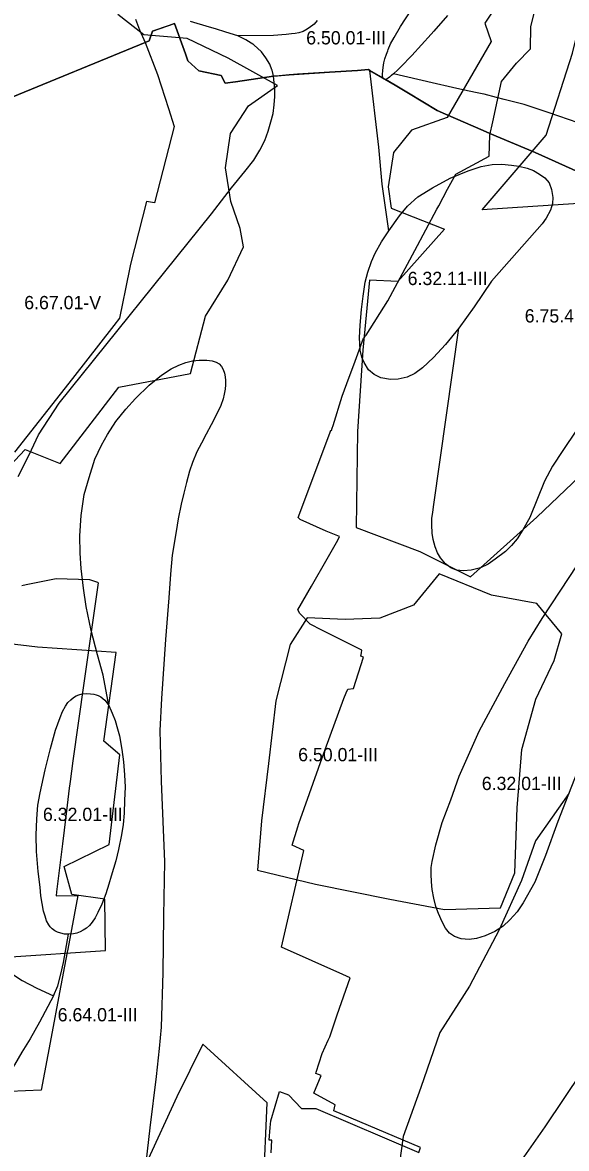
# Model space of a CAD drawing. Extents: x -555156 to -540209, y -1046851 to -1035695.
# Drawn here: x -543686 to -543276, y -1041405 to -1040556 of the extents above; entities that cross this region are included whole.
import ezdxf

# ---------------------------------------------------------------- set-up
doc = ezdxf.new("R2010")
doc.units = 0
for name, color, linetype in [('Vrstva 12', 7, 'Continuous'), ('Vrstva 27', 7, 'Continuous'), ('Vrstva 28', 7, 'Continuous'), ('Vrstva 29', 7, 'Continuous')]:
    doc.layers.add(name, color=color, linetype=linetype)

msp = doc.modelspace()

# ---------------------------------------------------------------- linework, layer by layer
at = {"layer": 'Vrstva 12'}
for points in [[(-543498.53, -1041408.44), (-543497.81, -1041398.96), (-543499.81, -1041398.89), (-543499.08, -1041389.42), (-543498.7, -1041384.38), (-543492.02, -1041362.08), (-543485.34, -1041364.83), (-543475.49, -1041375.02), (-543464.74, -1041375.01), (-543386.99, -1041408.3), (-543385.74, -1041404.41), (-543451.18, -1041376.73), (-543450.07, -1041372.36), (-543466.16, -1041363.35), (-543460.73, -1041350.09), (-543464.77, -1041348.56), (-543464.41, -1041347.63), (-543459.93, -1041333.56), (-543455.39, -1041323.59), (-543454.25, -1041321.08), (-543448.53, -1041304.5), (-543438.87, -1041276.51), (-543444.45, -1041273.91), (-543490.62, -1041253.26), (-543473.78, -1041180.39), (-543482.45, -1041176.48), (-543478.32, -1041162.62), (-543477.44, -1041160.15), (-543458.7, -1041107.1), (-543457.94, -1041105.02), (-543457.66, -1041104.26), (-543443.69, -1041065.97), (-543441.85, -1041061.61), (-543440.65, -1041058.78), (-543436.23, -1041058.23), (-543428.67, -1041034.6), (-543430.7, -1041033.81), (-543430.31, -1041031.4), (-543429.99, -1041029.48), (-543454.04, -1041017.4), (-543460.13, -1041014.34), (-543468.96, -1041009.9), (-543476.75, -1041001.8), (-543478.2, -1040998.98), (-543468, -1040981.18), (-543456.25, -1040960.65), (-543448.12, -1040946.45), (-543446.912347, -1040943.566929), (-543456.92, -1040939.75), (-543476.44, -1040930.98), (-543478.04, -1040929.37), (-543454.19, -1040865.7), (-543453.37, -1040863.52), (-543452.79, -1040863.73), (-543452.28, -1040862.01), (-543451.66, -1040859.91), (-543444.94, -1040837.84), (-543441.39, -1040828.27), (-543435.13, -1040811.43), (-543428.68, -1040794.07), (-543426.78, -1040791.75), (-543410.45, -1040765.88), (-543390.01, -1040727.91), (-543373.27, -1040696.81), (-543371.93, -1040694.31), (-543365.25, -1040681.9), (-543359.07, -1040670.43), (-543333.92, -1040656.78), (-543333.49, -1040641.01), (-543331.24, -1040631.05), (-543324.56, -1040600.61), (-543313.33, -1040586.75), (-543302.82, -1040575.86), (-543302.36, -1040559.22), (-543297.93, -1040541.28)], [(-543600.86, -1040553.7), (-543597.77, -1040561.73), (-543593.47, -1040571.22), (-543584.26, -1040595.42), (-543575.95, -1040621.03), (-543571.55, -1040634.6), (-543586.56, -1040692.2), (-543592.51, -1040691.16)], [(-543592.51, -1040691.16), (-543604.48, -1040738.44), (-543608.53, -1040758.07), (-543610.32, -1040766.76), (-543612.86, -1040779.08), (-543617.16, -1040784.58), (-543648.44, -1040824.55), (-543691.97, -1040880.16)], [(-543686.62, -1040980.68), (-543683.27, -1040979.99), (-543660.69, -1040975.32), (-543635.43, -1040976.2), (-543629.34, -1040978.2), (-543629.01, -1040978.73), (-543639.72, -1041054.36), (-543648.01, -1041112.9), (-543650.18, -1041128.46), (-543650.42, -1041130.19), (-543650.87, -1041133.37), (-543653.47, -1041154.92), (-543655.95, -1041175.43), (-543660.32, -1041211.61), (-543660.69, -1041214.71), (-543644.41, -1041214.39), (-543651.97, -1041254.77), (-543652.44, -1041257.25), (-543658.14, -1041287.58), (-543664.44, -1041321.12), (-543671.97, -1041361.22), (-543719.58, -1041363.23)]]:
    msp.add_lwpolyline(points, dxfattribs=at)
at = {"layer": 'Vrstva 28'}
for points in [[(-543413.96, -1040590.05), (-543413.45, -1040586.63), (-543412.6, -1040583.56), (-543411.32, -1040579.97), (-543410.42, -1040577.52), (-543410.04, -1040576.47), (-543408.24, -1040572.2), (-543405.68, -1040567.33), (-543400.9, -1040559.18), (-543392.87, -1040546.69)], [(-543365.44, -1040550.9), (-543375.76, -1040562.6), (-543377.75, -1040564.86), (-543392.24, -1040581), (-543393.44, -1040582.34), (-543399.32, -1040588.34), (-543402.79, -1040591.8), (-543406.05, -1040594.73)], [(-543702.42, -1040808.65), (-543708.38, -1040743.94), (-543710.96, -1040724.1), (-543714.65, -1040695.64), (-543715.21, -1040672.48), (-543732.41, -1040662.28), (-543766.58, -1040642.03), (-543740.61, -1040631.41), (-543698.83, -1040614.32), (-543593.47, -1040571.22), (-543590.56, -1040569.96), (-543587.92, -1040562.74), (-543571.38, -1040556.86), (-543563.03, -1040579.77)], [(-543496.57, -1040596.65), (-543525.27, -1040600.79), (-543533.08, -1040601.92), (-543536.12, -1040596.1), (-543552.9, -1040592.63), (-543561.17, -1040584.9), (-543563.03, -1040579.77), (-543571.38, -1040556.86), (-543575.41, -1040558.29), (-543587.92, -1040562.74), (-543590.56, -1040569.96), (-543593.47, -1040571.22), (-543698.83, -1040614.32)], [(-543523.53, -1040566.26), (-543532.64, -1040563.27), (-543540.46, -1040560.92), (-543545.04, -1040559.54), (-543559.37, -1040555.25)], [(-543463.73, -1040554.68), (-543466.04, -1040557.24), (-543467.03, -1040558.07), (-543468.6, -1040559.38), (-543471.25, -1040561.17), (-543474.32, -1040562.79), (-543477.56, -1040563.9), (-543480.38, -1040564.41), (-543482.94, -1040564.76), (-543487.21, -1040565.18), (-543496.6, -1040565.78), (-543523.53, -1040566.26)], [(-543496.57, -1040596.65), (-543496.9, -1040595.35), (-543497.71, -1040592.16), (-543497.84, -1040591.67), (-543499.33, -1040587.63), (-543502.32, -1040582.7), (-543505.61, -1040578.22), (-543511.58, -1040572.84), (-543511.85, -1040572.67), (-543512.26, -1040572.42), (-543513.49, -1040571.66), (-543517.41, -1040569.25), (-543523.53, -1040566.26)], [(-543563.03, -1040579.77), (-543561.17, -1040584.9), (-543552.9, -1040592.63), (-543536.12, -1040596.1), (-543533.08, -1040601.92), (-543525.27, -1040600.79), (-543496.57, -1040596.65)], [(-543689.29, -1040898.52), (-543681.03, -1040882.19), (-543673.88, -1040867.03), (-543658.41, -1040843.09), (-543543.36, -1040700.5), (-543528.22, -1040680.75), (-543518.29, -1040668.51), (-543511.51, -1040659.9), (-543507.03, -1040652.27), (-543503.28, -1040645), (-543500.61, -1040638.09), (-543498.55, -1040630.94), (-543496.98, -1040624.64), (-543496.13, -1040618.22), (-543495.53, -1040611.92), (-543495.65, -1040606.47), (-543496.57, -1040596.65)], [(-543496.57, -1040596.65), (-543484.82, -1040595.49), (-543454.33, -1040593.48), (-543433.19, -1040592.18), (-543425.03, -1040591.54), (-543423.93, -1040592.18)], [(-543413.87, -1040598.02), (-543423.93, -1040592.18), (-543425.03, -1040591.54), (-543433.19, -1040592.18), (-543454.33, -1040593.48), (-543478.66, -1040595.08), (-543484.82, -1040595.49), (-543492.41, -1040596.24), (-543496.57, -1040596.65)], [(-543409.7, -1040713.2), (-543414.52, -1040677.95), (-543417.12, -1040650.12), (-543423.93, -1040592.18)], [(-543423.93, -1040592.18), (-543404.86, -1040603.25)], [(-543413.87, -1040598.02), (-543414.06, -1040597.53), (-543414.28, -1040596.22), (-543414.34, -1040594.55), (-543414.23, -1040592.99), (-543414.16, -1040592.21), (-543413.96, -1040590.05)], [(-543406.05, -1040594.73), (-543407.57, -1040595.99), (-543407.76, -1040596.15), (-543409.1, -1040597.21), (-543410.16, -1040598), (-543410.97, -1040598.56), (-543411.41, -1040598.84), (-543411.75, -1040598.97)], [(-543091.12, -1040712.41), (-543111.91, -1040700.84), (-543134.91, -1040687.76), (-543164.45, -1040672.33), (-543174.27, -1040667.88), (-543176.28, -1040666.97), (-543193.18, -1040659.82), (-543201.63, -1040656.25), (-543228.82, -1040646.05), (-543266.64, -1040631.83), (-543288.6, -1040624.24), (-543307.42, -1040617.96), (-543322.58, -1040614.04), (-543328.36, -1040612.54), (-543337.74, -1040610.12), (-543337.84, -1040610.1), (-543342.85, -1040609.11), (-543353.68, -1040606.98), (-543361.64, -1040605.12), (-543376.95, -1040601.54), (-543406.05, -1040594.73)], [(-543412.12, -1040599.04), (-543413.87, -1040598.02)], [(-543411.75, -1040598.97), (-543412.12, -1040599.04)], [(-543085.78, -1040738.2), (-543101.67, -1040732.49), (-543140.14, -1040717.52), (-543174.28, -1040705.94), (-543210.23, -1040692.22), (-543217.71, -1040689.38), (-543238.43, -1040681.52), (-543299.21, -1040654.19), (-543333.45, -1040639.76), (-543338.53, -1040637.62), (-543366.74, -1040625.24), (-543373.17, -1040622.42), (-543394.76, -1040609.36), (-543404.86, -1040603.25), (-543412.12, -1040599.04)], [(-543404.86, -1040603.25), (-543394.76, -1040609.36), (-543373.17, -1040622.42), (-543366.74, -1040625.24), (-543338.53, -1040637.62), (-543333.45, -1040639.76), (-543299.21, -1040654.19), (-543238.43, -1040681.52), (-543217.71, -1040689.38), (-543210.23, -1040692.22), (-543174.28, -1040705.94), (-543140.14, -1040717.52), (-543101.67, -1040732.49), (-543085.78, -1040738.2)], [(-543409.7, -1040713.2), (-543401.56, -1040701.79), (-543395.62, -1040694.52), (-543387.63, -1040687.61), (-543376.61, -1040680.82), (-543363.29, -1040673.43), (-543349.84, -1040667.86), (-543340.03, -1040664.59), (-543331.68, -1040663.13), (-543324.29, -1040662.89), (-543317.14, -1040663.62)], [(-543317.14, -1040663.62), (-543311.45, -1040664.35), (-543305.16, -1040666.04), (-543300.43, -1040667.62), (-543295.83, -1040670.4), (-543291.83, -1040673.31), (-543288.56, -1040677.07), (-543286.75, -1040682.04), (-543285.9, -1040687.97), (-543286.02, -1040692.58), (-543287.72, -1040697.55), (-543290.99, -1040703.73), (-543293.97, -1040708.02), (-543332.07, -1040751.25), (-543345.15, -1040770.52), (-543356.78, -1040786.63)], [(-543356.78, -1040786.63), (-543366.95, -1040798.99), (-543375.91, -1040808.69), (-543384.15, -1040816.44), (-543390.08, -1040820.68), (-543395.78, -1040823.59), (-543402.56, -1040825.17), (-543408.37, -1040825.41), (-543415.64, -1040824.08), (-543420.72, -1040821.65), (-543425.08, -1040817.9), (-543428.35, -1040812.44), (-543430.05, -1040808.57), (-543431.14, -1040803.11), (-543431.62, -1040798.27), (-543431.68, -1040793.9), (-543431.19, -1040784.21), (-543430.34, -1040772.58), (-543428.89, -1040762.4), (-543427.44, -1040751.86), (-543425.5, -1040744.35), (-543422.71, -1040736.35), (-543419.93, -1040730.05), (-543415.08, -1040721.44), (-543409.7, -1040713.2)], [(-543268, -1040863.45), (-543278.38, -1040878.72), (-543286.23, -1040890.59), (-543292.22, -1040901.95), (-543303.12, -1040929.34), (-543308.45, -1040938.67), (-543312.69, -1040945.33), (-543316.93, -1040950.54), (-543321.53, -1040955.03), (-543329.28, -1040960.72), (-543334.73, -1040964.48), (-543340.54, -1040967.39), (-543347.57, -1040968.96), (-543353.38, -1040969.69), (-543358.47, -1040969.08), (-543362.83, -1040967.39), (-543366.94, -1040964.24), (-543370.58, -1040959.87), (-543372.88, -1040956.12), (-543374.69, -1040951.39), (-543376.15, -1040946.06), (-543376.87, -1040941.09), (-543377.12, -1040934.79), (-543377.12, -1040930.19), (-543376.51, -1040925.22), (-543375.75, -1040919.57), (-543356.78, -1040786.63)], [(-543621.02, -1041071.14), (-543625.26, -1041048.24), (-543629.5, -1041032.97), (-543634.16, -1041014.52), (-543637.98, -1040996.49), (-543640.1, -1040982.71), (-543641.81, -1040967.83), (-543642.65, -1040956.38), (-543642.87, -1040943.23), (-543641.81, -1040927.75), (-543639.47, -1040912.06), (-543635.87, -1040899.12), (-543631.42, -1040885.34), (-543626.55, -1040874.74), (-543621.88, -1040866.68), (-543615.53, -1040856.92), (-543608.11, -1040847.59), (-543600.85, -1040839.67), (-543590.43, -1040829.62), (-543581.23, -1040821.98), (-543573.84, -1040817.26), (-543568.03, -1040814.59), (-543562.82, -1040812.53), (-543557.86, -1040811.32), (-543552.65, -1040810.71), (-543547.08, -1040810.83)], [(-543547.08, -1040810.83), (-543542.91, -1040811.27), (-543539.86, -1040812.17), (-543537.58, -1040813.55), (-543535.78, -1040815.42), (-543534.53, -1040817.71), (-543533.57, -1040820.48), (-543533.01, -1040823.31), (-543532.8, -1040825.95), (-543532.94, -1040829.34), (-543533.22, -1040832.59), (-543533.84, -1040836.26), (-543534.67, -1040839.93), (-543536.33, -1040844.85), (-543539.66, -1040851.77), (-543543.74, -1040859.6), (-543547.49, -1040866.57), (-543551.09, -1040873.22), (-543554.41, -1040879.87), (-543557.67, -1040887.83), (-543560.11, -1040894.52), (-543562.41, -1040903), (-543564.35, -1040911), (-543566.29, -1040919.24), (-543568.59, -1040930.27), (-543570.16, -1040939.84), (-543573.12, -1040957.74), (-543574.39, -1040972.16), (-543575.66, -1040989.97), (-543578.21, -1041021.36), (-543581.17, -1041065.89), (-543582.45, -1041090.06), (-543581.53, -1041128.11), (-543578.94, -1041188.97), (-543579.68, -1041229.79), (-543580.05, -1041272.47), (-543581.53, -1041313.66), (-543583.02, -1041329.8), (-543585.24, -1041350.95), (-543590.06, -1041389.55), (-543594.14, -1041427.03)], [(-543267.79, -1041121.9), (-543281.99, -1041158.59), (-543291.42, -1041184.35), (-543299.54, -1041204.34), (-543308.14, -1041219.86), (-543312.86, -1041226.64), (-543318.31, -1041232.82), (-543323.27, -1041237.43), (-543329.57, -1041241.54), (-543336.84, -1041244.82), (-543343.38, -1041246.76), (-543348.95, -1041247.6), (-543355, -1041247), (-543360.09, -1041245.3), (-543363.85, -1041242.76), (-543366.75, -1041239.12), (-543369.42, -1041234.15), (-543372.08, -1041227.85), (-543374.02, -1041222.76), (-543375.71, -1041216.34), (-543376.92, -1041209.8), (-543377.29, -1041204.1), (-543377.65, -1041198.29), (-543377.65, -1041193.32), (-543376.83, -1041188.83), (-543374.08, -1041176.1), (-543369.42, -1041159.35), (-543362.85, -1041142.18), (-543356.49, -1041124.36), (-543341.44, -1041090.54), (-543322.15, -1041054.55), (-543304.35, -1041022.63), (-543293.87, -1041005.52), (-543253.63, -1040944.47)], [(-543651.37, -1041243.65), (-543652.74, -1041243.66), (-543654.24, -1041243.59), (-543657.17, -1041242.91), (-543659.58, -1041242.12), (-543661.72, -1041241.13), (-543663.58, -1041239.63), (-543665.08, -1041238.05), (-543666.23, -1041236.58), (-543667.83, -1041233.47), (-543669.07, -1041230.07), (-543670.11, -1041226.2), (-543671.29, -1041220.38), (-543672.12, -1041214.63), (-543672.83, -1041208.18), (-543674.28, -1041196.19), (-543675.49, -1041181.16), (-543675.74, -1041168.8), (-543675.25, -1041156.56), (-543674.4, -1041146.27), (-543672.68, -1041136.88), (-543668.92, -1041119.68), (-543664.93, -1041103.56), (-543661.14, -1041089.62), (-543657.7, -1041080.21), (-543655.92, -1041075.62), (-543653.71, -1041071.54), (-543651.73, -1041068.81), (-543649.6, -1041066.75), (-543647.58, -1041065.13), (-543645.56, -1041063.94), (-543643.55, -1041063.03), (-543641.09, -1041062.44), (-543638.13, -1041062.2), (-543634.65, -1041062.28)], [(-543634.65, -1041062.28), (-543632.28, -1041062.6), (-543630.46, -1041062.99), (-543628.84, -1041063.67), (-543627.02, -1041064.7), (-543625.51, -1041065.8), (-543623.85, -1041067.15), (-543622.9, -1041068.37), (-543621.02, -1041071.14)], [(-543621.02, -1041071.14), (-543618.31, -1041076.98), (-543616.25, -1041082.43), (-543614.43, -1041088.61), (-543612.98, -1041094.06), (-543611.16, -1041104.24), (-543609.95, -1041113.57), (-543609.1, -1041123.51), (-543608.65, -1041132.6), (-543609.01, -1041142.42), (-543609.38, -1041152.35), (-543610.1, -1041160.84), (-543611.31, -1041168.59), (-543613.61, -1041179.62), (-543615.67, -1041188.22), (-543619.14, -1041199.93), (-543620.94, -1041205.82), (-543623.16, -1041213.02), (-543626.27, -1041220.98), (-543629.18, -1041227.21), (-543631.32, -1041231.23), (-543633.4, -1041234.48), (-543635.61, -1041237.11), (-543637.83, -1041239.12), (-543640.18, -1041240.58), (-543642.53, -1041241.75), (-543644.95, -1041242.72), (-543647.52, -1041243.28), (-543651.37, -1041243.65)], [(-543367.43, -1041496.06), (-543358.52, -1041484.25), (-543291.66, -1041388.79), (-543235.84, -1041305.67), (-543212.48, -1041277.09), (-543186.52, -1041230.33), (-543130.8, -1041093.03)], [(-543805.56, -1041178.33), (-543801.54, -1041178.79), (-543794.15, -1041180.49), (-543788.46, -1041182.31), (-543781.92, -1041185.21), (-543774.9, -1041189.09), (-543768.48, -1041193.94), (-543763.27, -1041198.54), (-543758.31, -1041204), (-543750.56, -1041213.33), (-543742.85, -1041221.98), (-543723.35, -1041244.88), (-543707.45, -1041261.21), (-543695.16, -1041272.66), (-543686.26, -1041278.59), (-543675.24, -1041284.32), (-543662.75, -1041290.03)], [(-543662.75, -1041290.03), (-543659.48, -1041282.39), (-543657.06, -1041273.67), (-543655.12, -1041264.82), (-543651.37, -1041243.65)], [(-543662.75, -1041290.03), (-543673.29, -1041310.02), (-543680.19, -1041322.38), (-543686.61, -1041332.56), (-543691.99, -1041342.1), (-543697.44, -1041352.64), (-543703.01, -1041364.76), (-543708.22, -1041379.06), (-543712.09, -1041390.81), (-543714.76, -1041402.93)]]:
    msp.add_lwpolyline(points, dxfattribs=at)
at = {"layer": 'Vrstva 29'}
for points in [[(-543203.043003, -1040533.644997), (-543205.959003, -1040596.590006), (-543203.105995, -1040684.815999), (-543266.397004, -1040692.522995), (-543339.110996, -1040697.288998), (-543290.863999, -1040640.979001), (-543270.945994, -1040579.150993), (-543247.329994, -1040483.771991)], [(-543303.915998, -1040506.907994), (-543337.225003, -1040556.489998), (-543332.424005, -1040570.462007), (-543365.693999, -1040627.695991), (-543392.403006, -1040637.375992), (-543406.000005, -1040654.175001), (-543409.990991, -1040680.050991), (-543407.936005, -1040696.054005), (-543367.565993, -1040711.900992), (-543402.721998, -1040751.363998), (-543424.326002, -1040750.315995), (-543429.342999, -1040803.116992), (-543433.379997, -1040864.424996), (-543434.147994, -1040937.007992), (-543386.329993, -1040955.098005), (-543348.076009, -1040974.072), (-543297.815007, -1040929.155006), (-543228.173006, -1040862.656001)], [(-543703.723999, -1040898.708984), (-543684.151978, -1040878.14801), (-543657.567993, -1040888.596008), (-543613.296997, -1040831.140015), (-543559.200989, -1040820.768005), (-543547.938904, -1040777.487), (-543531.057007, -1040750.296021), (-543519.221985, -1040725.169983), (-543521.745911, -1040711.416992), (-543528.754028, -1040691.116028), (-543532.981018, -1040665.728027), (-543528.98999, -1040639.851013), (-543515.515015, -1040618.961975), (-543493.640015, -1040603.721008), (-543530.747009, -1040583.086975), (-543561.755005, -1040568.137024), (-543594.445007, -1040565.516907), (-543614.174988, -1040550.117004)], [(-543279.106018, -1041017.114014), (-543297.862976, -1040994.158997), (-543332.240906, -1040987.809021), (-543371.575989, -1040971.805969), (-543390.929993, -1040995.447021), (-543416.374023, -1041005.247986), (-543442.52002, -1041006.313904), (-543471.257019, -1041005.093018), (-543484.130005, -1041025.02002), (-543494.812988, -1041067.591003), (-543500.314026, -1041114.737), (-543505.708008, -1041158.070007), (-543508.72998, -1041195.255981), (-543465.047913, -1041205.810913), (-543408.919006, -1041217.047913), (-543367.528015, -1041224.835022), (-543325.39502, -1041223.718018), (-543314.606018, -1041197.27002), (-543312.757019, -1041148.244019), (-543309.340027, -1041104.211975), (-543298.583008, -1041066.237), (-543284.846008, -1041037.214905), (-543279.106018, -1041017.114014)], [(-543698.562012, -1041260.956909), (-543623.521912, -1041255.903992), (-543623.922913, -1041217.11499), (-543648.877991, -1041213.705994), (-543654.525024, -1041192.515991), (-543620.768982, -1041175.862), (-543612.565979, -1041108.325012), (-543624.606018, -1041097.994995), (-543615.437988, -1041031.059021), (-543674.817993, -1041027.158997), (-543721.281006, -1041021.692017)], [(-543273.686001, -1041137.452995), (-543299.047992, -1041173.264992), (-543309.544008, -1041203.108006), (-543326.349998, -1041240.249006), (-543348.769004, -1041282.716994), (-543371.251998, -1041317.784993), (-543385.406005, -1041359.259001), (-543398.873997, -1041396.210009), (-543403.992999, -1041433.959995), (-543404.442993, -1041456.304994), (-543395.594996, -1041486.406998), (-543382.323, -1041530.674999), (-543385.770001, -1041534.437222), (-543380.911011, -1041551.145996), (-543400.126469, -1041563.267395), (-543401.121997, -1041570.371005), (-543396.906003, -1041598.562003), (-543384.738999, -1041623.690993), (-543362.317008, -1041651.075995), (-543336.944003, -1041676.959003), (-543291.658998, -1041689.453), (-543223.514994, -1041705.918994)], [(-543504.097003, -1041434.065001), (-543501.410005, -1041370.843008), (-543550.044004, -1041326.417009), (-543569.644999, -1041366.095002), (-543592.507995, -1041415.913009)]]:
    msp.add_lwpolyline(points, dxfattribs=at)

# ---------------------------------------------------------------- texts
at = {"layer": 'Vrstva 27'}
for s, p in [('6.50.01-III', (-543471.961963, -1040572.62)), ('6.32.11-III', (-543395.386548, -1040754.09)), ('6.67.01-V', (-543684.741006, -1040772.3)), ('6.75.41-V', (-543307.051006, -1040782.31)), ('6.50.01-III', (-543478.036548, -1041113.17)), ('6.32.01-III', (-543339.466548, -1041134.88)), ('6.32.01-III', (-543670.626548, -1041158.19)), ('6.64.01-III', (-543659.496548, -1041309.3))]:
    msp.add_text(s, height=10, dxfattribs=at).set_placement(p)

doc.saveas('drawing.dxf')
